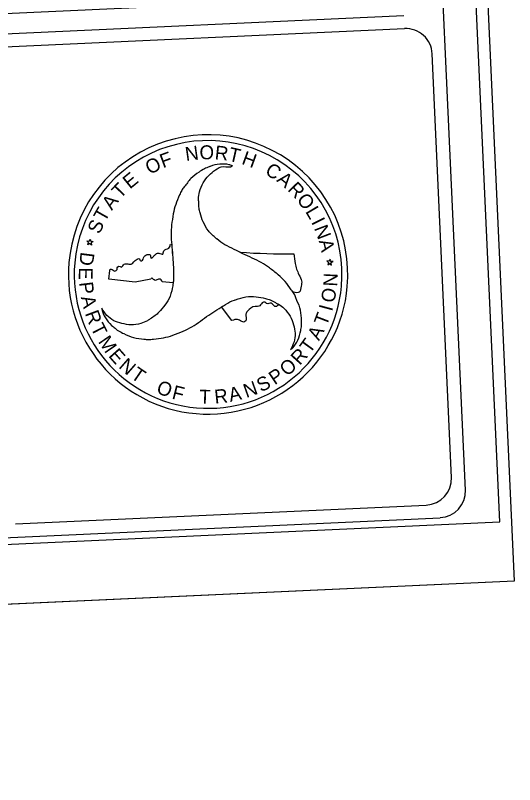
# Model space of a CAD drawing. Extents: x 1190067 to 1192950, y 891516 to 893460.
# Drawn here: x 1192875.1 to 1192950.4, y 892906.1 to 893022.3 of the extents above; entities that cross this region are included whole.
import ezdxf

# ---------------------------------------------------------------- set-up
doc = ezdxf.new("R2010")
doc.units = 0
for name, color, linetype in [('Sheet Cutting Line CELL', 7, 'Continuous'), ('Sheet Plot Border Inside CELL', 7, 'Continuous'), ('Sheet Plot Border Outside CELL', 7, 'Continuous'), ('Sheet Sticker Exception Certification CELL', 7, 'Continuous'), ('Sheet Title CELL', 7, 'Continuous')]:
    doc.layers.add(name, color=color, linetype=linetype)

# ---------------------------------------------------------------- blocks, each defined once
blk = doc.blocks.new('STICKER EXCEPTION CERTIFICATION')
at = {"layer": 'Sheet Sticker Exception Certification CELL'}
for p, q in [((0, -0.47), (0, 0)), ((0, 0), (4.0008, 0)), ((4.0008, -0.0003), (4.0008, -0.4703)), ((4.0008, -0.47), (0, -0.47))]:
    blk.add_line(p, q, dxfattribs=at)
for s, p in [('DOCUMENT NOT CONSIDERED FINAL', (0.4214, -0.2069)), ('UNLESS ALL SIGNATURES COMPLETED', (0.32, -0.3829))]:
    blk.add_text(s, height=0.11, dxfattribs=at).set_placement(p)

msp = doc.modelspace()

# ---------------------------------------------------------------- linework, layer by layer
at = {"layer": 'Sheet Cutting Line CELL'}
msp.add_line((1192277.54, 892906.14), (1192950.44, 892936.92), dxfattribs=at)
at = {"layer": 'Sheet Plot Border Inside CELL'}
msp.add_lwpolyline([(1192282.33, 892915.34), (1192948.23, 892945.8), (1192928.94, 893367.4), (1192263.04, 893336.94)], close=True, dxfattribs=at)
at = {"layer": 'Sheet Plot Border Outside CELL'}
msp.add_lwpolyline([(1192930.33, 893376.46), (1192257.43, 893345.67), (1192277.54, 892906.14), (1192950.44, 892936.92)], close=True, dxfattribs=at)
at = {"layer": 'Sheet Title CELL'}
for p, q in [((1192366.32, 892996.29), (1192933.72, 893022.25)), ((1192871.79, 893017.41), (1192933.81, 893020.25)), ((1192907.84, 892999.6), (1192907.8, 892999.56)), ((1192907.84, 892999.6), (1192907.8, 892999.56)), ((1192886.23, 892988.17), (1192886.36, 892988.49)), ((1192886.36, 892988.49), (1192886.46, 892988.15)), ((1192886.14, 892987.95), (1192885.87, 892988.2)), ((1192885.87, 892988.2), (1192886.23, 892988.17)), ((1192886, 892987.62), (1192886.14, 892987.95)), ((1192886.3, 892987.81), (1192886, 892987.62)), ((1192886.58, 892987.57), (1192886.3, 892987.81)), ((1192886.46, 892988.15), (1192886.82, 892988.12)), ((1192886.82, 892988.12), (1192886.5, 892987.92)), ((1192886.5, 892987.92), (1192886.58, 892987.57)), ((1192908.97, 892986.5), (1192908.97, 892986.5)), ((1192922.43, 892985.14), (1192922.07, 892985.18)), ((1192922.07, 892985.18), (1192922.35, 892984.94)), ((1192922.35, 892984.94), (1192922.22, 892984.6)), ((1192922.58, 892985.47), (1192922.43, 892985.14)), ((1192922.67, 892985.12), (1192922.58, 892985.47)), ((1192923.03, 892985.11), (1192922.67, 892985.12)), ((1192922.71, 892984.91), (1192923.03, 892985.11)), ((1192922.79, 892984.55), (1192922.71, 892984.91)), ((1192889.2, 892982.46), (1192889.35, 892983.72)), ((1192922.22, 892984.6), (1192922.52, 892984.79)), ((1192922.52, 892984.79), (1192922.79, 892984.55)), ((1192893.17, 892981.96), (1192889.2, 892982.46)), ((1192895.51, 892982.44), (1192893.17, 892981.96)), ((1192898.91, 892981.86), (1192897.24, 892982.02)), ((1192925.18, 892981.33), (1192925.18, 892981.33)), ((1192907.77, 892976.18), (1192906.18, 892978.24)), ((1192906.18, 892978.24), (1192906.18, 892978.24))]:
    msp.add_line(p, q, dxfattribs=at)
for points in [[(1192943.01, 892950.6), (1192924.18, 893362.16)], [(1192940.92, 892952.5), (1192937.99, 893016.44)], [(1192875.08, 892945.49), (1192937.1, 892948.32)], [(1192347.81, 892919.36), (1192939.19, 892946.41)]]:
    msp.add_lwpolyline(points, dxfattribs=at)
for centre, radius, start, end in [((1192934, 893016.27), 4, 2.6195, 92.6195), ((1192904.17, 892983.15), 21.09, 355.0406, 175.0406), ((1192904.17, 892983.15), 20.21, 355.0406, 175.0406), ((1192916.42, 893097.43), 111.18, 260.7191, 260.8187), ((1192916.42, 893097.43), 111.18, 266.1581, 270.3642), ((1192904.17, 892983.15), 21.09, 175.0406, 355.0406), ((1192904.17, 892983.15), 20.21, 175.0406, 355.0406), ((1192936.92, 892952.34), 4, 272.6195, 2.6195), ((1192939.01, 892950.43), 4, 272.6195, 2.6195)]:
    msp.add_arc(centre, radius, start, end, dxfattribs=at)
for points in [[(1192907.8, 892999.56), (1192907.34, 892999.72), (1192905.94, 892999.79), (1192904.48, 892999.46), (1192904.35, 892999.4), (1192903.61, 892999.09), (1192902.8, 892998.59), (1192901.57, 892997.61), (1192900.58, 892996.36), (1192900.19, 892995.83), (1192899.87, 892995.15), (1192899.28, 892993.71), (1192898.91, 892992.3), (1192898.67, 892990.63), (1192898.57, 892989.16), (1192898.68, 892987.64), (1192898.81, 892986.1), (1192898.9, 892984.61), (1192898.97, 892983.08), (1192898.85, 892981.58), (1192898.83, 892981.45), (1192898.43, 892979.88), (1192897.66, 892978.53), (1192896.72, 892977.43), (1192896.18, 892976.93), (1192895.43, 892976.44), (1192895, 892976.16), (1192894.01, 892975.75), (1192892.54, 892975.54), (1192891.14, 892975.75), (1192889.92, 892976.17), (1192888.89, 892976.97), (1192888.11, 892978.05)], [(1192916.59, 892971.76), (1192916.95, 892972.07), (1192917.71, 892973.25), (1192918.16, 892974.68), (1192918.19, 892974.82), (1192918.27, 892975.62), (1192918.25, 892976.57), (1192918.03, 892978.13), (1192917.42, 892979.6), (1192917.17, 892980.22), (1192916.73, 892980.84), (1192915.79, 892982.07), (1192914.75, 892983.09), (1192913.42, 892984.13), (1192912.2, 892984.94), (1192910.82, 892985.63), (1192909.43, 892986.27), (1192908.11, 892986.93), (1192906.72, 892987.64), (1192905.5, 892988.5), (1192905.4, 892988.59), (1192904.22, 892989.73), (1192903.44, 892991.07), (1192902.95, 892992.43), (1192902.81, 892993.13), (1192902.76, 892994.03), (1192902.71, 892994.55), (1192902.88, 892995.61), (1192903.42, 892996.99), (1192904.29, 892998.09), (1192905.27, 892998.93), (1192906.49, 892999.43), (1192907.8, 892999.56), (1192907.84, 892999.6)], [(1192889.35, 892983.72), (1192889.32, 892983.84), (1192889.54, 892983.96), (1192890.11, 892983.66), (1192890.43, 892983.89), (1192890.44, 892984.15), (1192890.7, 892984.39), (1192891.1, 892984.27), (1192891.51, 892984.7), (1192891.85, 892984.76), (1192892.56, 892984.69), (1192893.47, 892985.47), (1192893.83, 892985.49), (1192893.9, 892985.26), (1192894.11, 892985.19), (1192894.54, 892985.86), (1192894.64, 892985.95), (1192895.32, 892986.15), (1192895.48, 892986.02), (1192895.51, 892985.7), (1192895.59, 892985.63), (1192895.83, 892985.77), (1192896.15, 892986.11), (1192896.72, 892986.35), (1192897.33, 892986.22), (1192897.48, 892986.71), (1192898.24, 892987.14), (1192898.42, 892987.42), (1192898.48, 892987.71)], [(1192898.68, 892987.68), (1192898.68, 892987.64), (1192898.81, 892986.1), (1192898.9, 892984.61), (1192898.97, 892983.08), (1192898.9, 892981.86)], [(1192917.03, 892980.46), (1192916.73, 892980.84), (1192915.79, 892982.07), (1192914.75, 892983.09), (1192913.42, 892984.13), (1192912.2, 892984.94), (1192910.82, 892985.63), (1192909.43, 892986.27), (1192908.97, 892986.5)], [(1192917.12, 892986.25), (1192917.3, 892984.82), (1192917.89, 892983.11), (1192918.29, 892982.17), (1192918.21, 892981.39), (1192917.94, 892980.48), (1192917.04, 892980.46)], [(1192897.24, 892982.02), (1192897.11, 892982.34), (1192896.79, 892982.46), (1192896.34, 892982.27), (1192896.01, 892982.32), (1192895.67, 892982.61), (1192895.51, 892982.44)], [(1192888.11, 892978.05), (1192888.22, 892977.57), (1192888.86, 892976.32), (1192889.87, 892975.22), (1192889.98, 892975.14), (1192890.63, 892974.64), (1192891.46, 892974.21), (1192892.93, 892973.61), (1192894.49, 892973.4), (1192895.15, 892973.31), (1192895.93, 892973.39), (1192897.44, 892973.59), (1192898.84, 892973.97), (1192900.42, 892974.6), (1192901.73, 892975.25), (1192903.01, 892976.11), (1192904.26, 892977), (1192905.51, 892977.81), (1192906.81, 892978.63), (1192908.16, 892979.29), (1192908.31, 892979.33), (1192909.88, 892979.77), (1192911.41, 892979.78), (1192912.82, 892979.53), (1192913.55, 892979.31), (1192914.32, 892978.89), (1192914.81, 892978.67), (1192915.64, 892978.01), (1192916.54, 892976.84), (1192917.07, 892975.54), (1192917.31, 892974.26), (1192917.14, 892972.96), (1192916.59, 892971.76)], [(1192906.18, 892978.24), (1192906.81, 892978.63), (1192908.16, 892979.29), (1192908.31, 892979.33), (1192909.88, 892979.77), (1192911.41, 892979.78), (1192912.82, 892979.53), (1192913.55, 892979.31), (1192914.32, 892978.89), (1192914.77, 892978.68)], [(1192914.76, 892978.68), (1192914.54, 892978.33), (1192914.22, 892978.33), (1192913.7, 892978.82), (1192913.01, 892978.74), (1192912.72, 892978.95), (1192912.51, 892978.97), (1192911.97, 892978.4), (1192911.28, 892978.31), (1192910.12, 892977.6), (1192909.86, 892977.15), (1192909.85, 892976.14), (1192909.57, 892975.96), (1192909.25, 892976.04), (1192908.6, 892976.36), (1192907.77, 892976.18)]]:
    msp.add_spline(points, degree=3, dxfattribs=at)

# ---------------------------------------------------------------- block references
at = {"layer": 'Sheet Sticker Exception Certification CELL', "xscale": 20.000000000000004, "yscale": 20, "rotation": 2.619466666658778}
msp.add_blockref('STICKER EXCEPTION CERTIFICATION', (1192854.41, 893031.05), dxfattribs=at)

# ---------------------------------------------------------------- texts
at = {"layer": 'Sheet Title CELL'}
for s, height, rotation, p in [('N', 2.1, 8.0244, (1192900.85, 893000.25)), ('O', 2.11, 0.5263, (1192902.88, 893000.52)), ('R', 2.1, 353.9163, (1192905.11, 893000.54)), ('T', 2.11, 347.2667, (1192907.11, 893000.33)), ('F', 2.11, 20.1113, (1192897.35, 892999.18)), ('H', 2.1, 340.182, (1192909.11, 892999.86)), ('O', 2.1, 27.2582, (1192895.36, 892998.17)), ('C', 2.1, 327.8396, (1192912.62, 892998.39)), ('E', 2.1, 39.1975, (1192892.36, 892995.96)), ('A', 2.1, 320.3426, (1192914.4, 892997.27)), ('T', 2.1, 46.3132, (1192890.94, 892994.48)), ('R', 2.1, 313.9787, (1192916.06, 892995.89)), ('A', 2.11, 53.3684, (1192889.64, 892992.73)), ('O', 2.11, 306.8591, (1192917.45, 892994.44)), ('T', 2.11, 60.4207, (1192888.6, 892990.96)), ('L', 2.1, 300.6254, (1192918.79, 892992.65)), ('S', 2.1, 66.7968, (1192887.8, 892989.12)), ('I', 2.11, 296.636, (1192919.69, 892991.07)), ('N', 2.1, 290.9359, (1192920.13, 892990.14)), ('A', 2.1, 283.504, (1192920.86, 892988.21)), ('D', 2.1, 262.8936, (1192884.95, 892986.61)), ('E', 2.09, 269.1815, (1192884.67, 892984.21)), ('N', 2.1, 87.2487, (1192923.64, 892981.29)), ('P', 2.1, 276.7139, (1192884.68, 892981.93)), ('O', 2.09, 80.0007, (1192923.22, 892978.78)), ('A', 2.1, 283.3065, (1192884.95, 892979.7)), ('I', 2.11, 74.8651, (1192922.88, 892977.48)), ('R', 2.1, 290.3751, (1192885.55, 892977.28)), ('T', 2.1, 69.2152, (1192922.05, 892975.25)), ('T', 2.1, 297.0256, (1192886.38, 892975.11)), ('A', 2.11, 62.1308, (1192920.91, 892973.04)), ('M', 2.1, 304.2607, (1192887.49, 892973)), ('T', 2.1, 54.0437, (1192919.54, 892971.09)), ('E', 2.1, 311.7274, (1192889.03, 892970.82)), ('R', 2.11, 47.9439, (1192918, 892969.34)), ('N', 2.11, 318.699, (1192890.56, 892969.14)), ('O', 2.11, 40.7548, (1192916.09, 892967.67)), ('T', 2.1, 325.541, (1192892.36, 892967.59)), ('P', 2.1, 34.0628, (1192914.23, 892966.39)), ('S', 2.09, 26.871, (1192912.16, 892965.33)), ('O', 2.1, 338.8447, (1192896.22, 892965.31)), ('F', 2.1, 346.0099, (1192898.6, 892964.42)), ('N', 2.1, 19.6605, (1192909.94, 892964.48)), ('T', 2.1, 358.9191, (1192902.83, 892963.65)), ('R', 2.1, 5.8757, (1192905.22, 892963.63)), ('A', 2.1, 12.6289, (1192907.52, 892963.9))]:
    msp.add_text(s, height=height, rotation=rotation, dxfattribs=at).set_placement(p)

doc.saveas('drawing.dxf')
